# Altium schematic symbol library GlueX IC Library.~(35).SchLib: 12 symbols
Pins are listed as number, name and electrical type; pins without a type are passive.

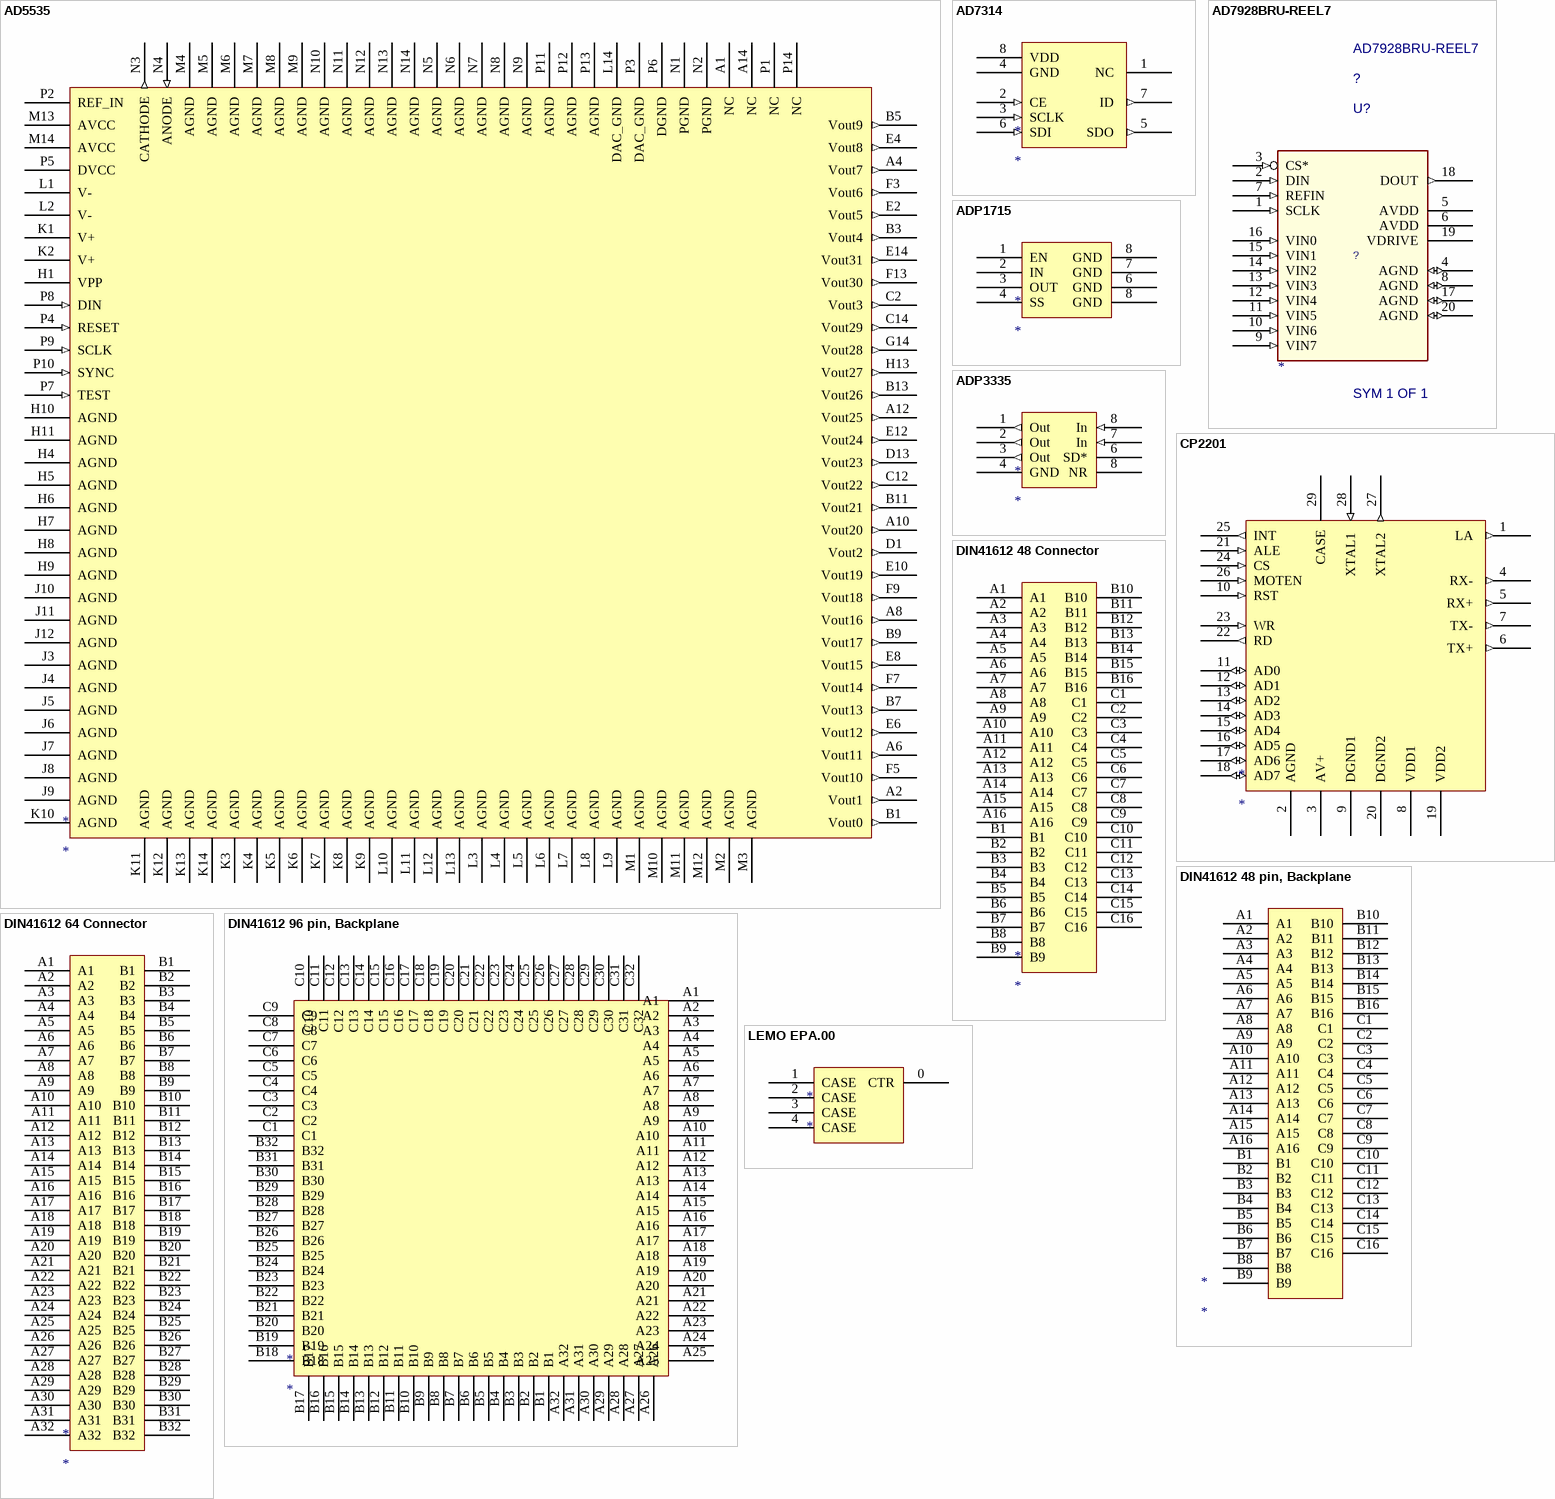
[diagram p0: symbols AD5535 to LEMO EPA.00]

## AD5535
designator *
footprint BC-124
pins: A1 NC, A2 Vout1 (out), A4 Vout7 (out), A6 Vout11 (out), A8 Vout16 (out), A10 Vout20 (out), A12 Vout25 (out), A14 NC, B1 Vout0 (out), B3 Vout4 (out), B5 Vout9 (out), B7 Vout13 (out), B9 Vout17 (out), B11 Vout21 (out), B13 Vout26 (out), C2 Vout3 (out), C12 Vout22 (out), C14 Vout29 (out), D1 Vout2 (out), D13 Vout23 (out), E2 Vout5 (out), E4 Vout8 (out), E6 Vout12 (out), E8 Vout15 (out), E10 Vout19 (out), E12 Vout24 (out), E14 Vout31 (out), F3 Vout6 (out), F5 Vout10 (out), F7 Vout14 (out), F9 Vout18 (out), F13 Vout30 (out), G14 Vout28 (out), H1 VPP (power), H4 AGND, H5 AGND, H6 AGND, H7 AGND, H8 AGND, H9 AGND, H10 AGND, H11 AGND, H13 Vout27 (out), J3 AGND, J4 AGND, J5 AGND, J6 AGND, J7 AGND, J8 AGND, J9 AGND, J10 AGND, J11 AGND, J12 AGND, K1 V+ (power), K2 V+ (power), K3 AGND, K4 AGND, K5 AGND, K6 AGND, K7 AGND, K8 AGND, K9 AGND, K10 AGND, K11 AGND, K12 AGND, K13 AGND, K14 AGND, L1 V- (power), L2 V- (power), L3 AGND, L4 AGND, L5 AGND, L6 AGND, L7 AGND, L8 AGND, L9 AGND, L10 AGND, L11 AGND, L12 AGND, L13 AGND, L14 DAC_GND, M1 AGND, M2 AGND, M3 AGND, M4 AGND, M5 AGND, M6 AGND, M7 AGND, M8 AGND, M9 AGND, M10 AGND, M11 AGND, M12 AGND, M13 AVCC (power), M14 AVCC (power), N1 PGND, N2 PGND, N3 CATHODE (out), N4 ANODE (in), N5 AGND, N6 AGND, N7 AGND, N8 AGND, N9 AGND, N10 AGND, N11 AGND, N12 AGND, N13 AGND, N14 AGND, P1 NC, P2 REF_IN (hiz), P3 DAC_GND, P4 RESET (in), P5 DVCC (power), P6 DGND, P7 TEST (in), P8 DIN (in), P9 SCLK (in), P10 SYNC (in), P11 AGND, P12 AGND, P13 AGND, P14 NC

## AD7314
designator *
footprint RM-8
pins: 1 NC , 2 CE (in), 3 SCLK  (in), 4 GND  (power), 5 SDO  (out), 6 SDI  (in), 7 ID  (out), 8 VDD  (power)

## AD7928BRU-REEL7
designator U?  SymName: AD7928BRU-REEL7  SlotXofY: SYM 1 OF 1
footprint RU-20
pins: 1 SCLK (in), 2 DIN (in), 3 CS* (in), 4 AGND (io), 5 AVDD (power), 6 AVDD (power), 7 REFIN (in), 8 AGND (io), 9 VIN7 (in), 10 VIN6 (in), 11 VIN5 (in), 12 VIN4 (in), 13 VIN3 (in), 14 VIN2 (in), 15 VIN1 (in), 16 VIN0 (in), 17 AGND (io), 18 DOUT (out), 19 VDRIVE (power), 20 AGND (io)

## ADP1715
designator *
footprint R-8_M (8-Pin Narrow Body Small Outline Integrated Circuit 1.27 mm Pitch, IPC Low Density)
pins: 1 EN, 2 IN, 3 OUT, 4 SS, 6 GND, 7 GND, 8 GND, 8 GND

## ADP3335
designator *
footprint R-8_M (8-Pin Narrow Body Small Outline Integrated Circuit 1.27 mm Pitch, IPC Low Density)
pins: 1 Out (out), 2 Out (out), 3 Out (out), 4 GND (power), 6 SD* (hiz), 7 In (in), 8 In (in), 8 NR

## CP2201
designator *
footprint QFN50P500X500-28W1L (QFN, 28-Leads, Body 5x5mm, Pitch 0.5mm, IPC High Density)
footprint QFN50P500X500-28V1N (QFN, 28-Leads, Body 5x5mm, Pitch 0.5mm, IPC Medium Density)
pins: 1 LA  (out), 2 AGND  (power), 3 AV+  (power), 4 RX-  (out), 5 RX+  (out), 6 TX+  (out), 7 TX-  (out), 8 VDD1  (power), 9 DGND1  (power), 10 RST  (in), 11 AD0  (io), 12 AD1  (io), 13 AD2  (io), 14 AD3  (io), 15 AD4  (io), 16 AD5  (io), 17 AD6  (io), 18 AD7  (io), 19 VDD2  (power), 20 DGND2  (power), 21 ALE  (in), 22 RD  (out), 23 WR  (in), 24 CS  (in), 25 INT  (out), 26 MOTEN  (in), 27 XTAL2  (out), 28 XTAL1  (in), 29 CASE (power)

## DIN41612 48 Connector
designator *
footprint EURO2.54-2H48 (Connector; DIN 41612, Type 2C, Thru-Hole; Rows a+b+c, 48 Position; Right Angle)
pins: A1, A2, A3, A4, A5, A6, A7, A8, A9, A10, A11, A12, A13, A14, A15, A16, B1, B2, B3, B4, B5, B6, B7, B8, B9, B10, B11, B12, B13, B14, B15, B16, C1, C2, C3, C4, C5, C6, C7, C8, C9, C10, C11, C12, C13, C14, C15, C16

## DIN41612 48 pin, Backplane
designator *
footprint EURO2.54-2V48 (Connector; DIN 41612, Type 2C, Thru-Hole; Rows a+b+c, 48 Position; Vertical)
pins: A1, A2, A3, A4, A5, A6, A7, A8, A9, A10, A11, A12, A13, A14, A15, A16, B1, B2, B3, B4, B5, B6, B7, B8, B9, B10, B11, B12, B13, B14, B15, B16, C1, C2, C3, C4, C5, C6, C7, C8, C9, C10, C11, C12, C13, C14, C15, C16

## DIN41612 64 Connector
designator *
footprint EURO2.54-2H64A (Connector; DIN 41612, Type B, Thru-Hole; Rows a+b, 64 Position; Right Angle)
pins: A1, A2, A3, A4, A5, A6, A7, A8, A9, A10, A11, A12, A13, A14, A15, A16, A17, A18, A19, A20, A21, A22, A23, A24, A25, A26, A27, A28, A29, A30, A31, A32, B1, B2, B3, B4, B5, B6, B7, B8, B9, B10, B11, B12, B13, B14, B15, B16, B17, B18, B19, B20, B21, B22, B23, B24, B25, B26, B27, B28, B29, B30, B31, B32

## DIN41612 96 pin, Backplane
designator *
footprint EURO2.54-2V96 (Connector; DIN 41612, Type C, Thru-Hole; Rows a+b+c, 96 Position; Vertical)
pins: A1, A2, A3, A4, A5, A6, A7, A8, A9, A10, A11, A12, A13, A14, A15, A16, A17, A18, A19, A20, A21, A22, A23, A24, A25, A26, A27, A28, A29, A30, A31, A32, B1, B2, B3, B4, B5, B6, B7, B8, B9, B10, B11, B12, B13, B14, B15, B16, B17, B18, B19, B20, B21, B22, B23, B24, B25, B26, B27, B28, B29, B30, B31, B32, C1, C2, C3, C4, C5, C6, C7, C8, C9, C10, C11, C12, C13, C14, C15, C16, C17, C18, C19, C20, C21, C22, C23, C24, C25, C26, C27, C28, C29, C30, C31, C32

## LEMO EPA.00
designator *
footprint PCBComponent_1
pins: 0 CTR, 1 CASE, 2 CASE, 3 CASE, 4 CASE

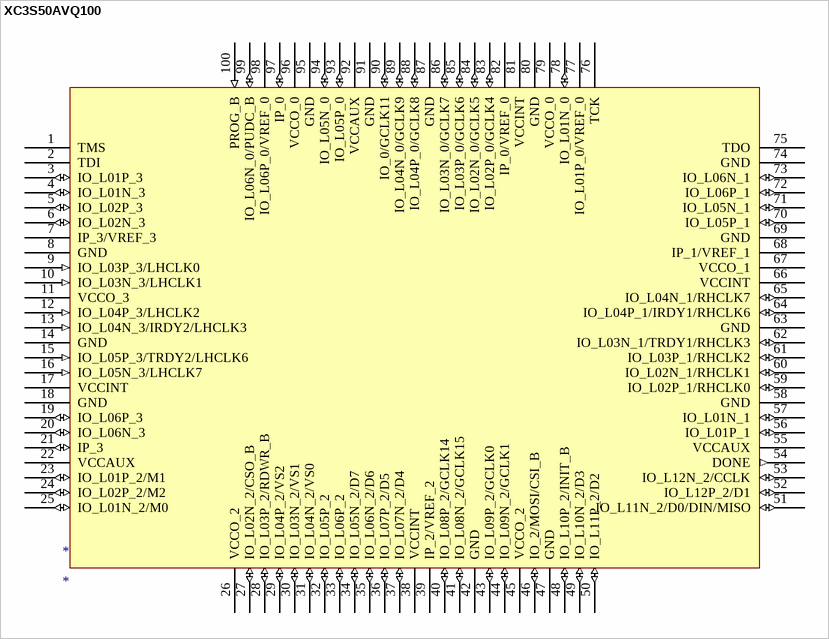
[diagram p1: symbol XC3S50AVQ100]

## XC3S50AVQ100
designator *
footprint VQ100_L (100-Pin Very Thin Quad Flat Pack (VQ100), IPC High Density)
pins: 1 TMS (power), 2 TDI (power), 3 IO_L01P_3 (io), 4 IO_L01N_3 (io), 5 IO_L02P_3 (io), 6 IO_L02N_3 (io), 7 IP_3/VREF_3 (hiz), 8 GND, 9 IO_L03P_3/LHCLK0 (in), 10 IO_L03N_3/LHCLK1 (in), 11 VCCO_3 (power), 12 IO_L04P_3/LHCLK2 (in), 13 IO_L04N_3/IRDY2/LHCLK3 (in), 14 GND (power), 15 IO_L05P_3/TRDY2/LHCLK6 (in), 16 IO_L05N_3/LHCLK7 (in), 17 VCCINT (power), 18 GND (power), 19 IO_L06P_3 (io), 20 IO_L06N_3 (io), 21 IP_3 (io), 22 VCCAUX (power), 23 IO_L01P_2/M1 (io), 24 IO_L02P_2/M2 (io), 25 IO_L01N_2/M0 (io), 26 VCCO_2 (power), 27 IO_L02N_2/CSO_B (io), 28 IO_L03P_2/RDWR_B (io), 29 IO_L04P_2/VS2 (io), 30 IO_L03N_2/VS1 (io), 31 IO_L04N_2/VS0 (io), 32 IO_L05P_2 (io), 33 IO_L06P_2 (io), 34 IO_L05N_2/D7 (io), 35 IO_L06N_2/D6 (io), 36 IO_L07P_2/D5 (io), 37 IO_L07N_2/D4 (io), 38 VCCINT (power), 39 IP_2/VREF_2 (hiz), 40 IO_L08P_2/GCLK14 (io), 41 IO_L08N_2/GCLK15 (io), 42 GND (power), 43 IO_L09P_2/GCLK0 (io), 44 IO_L09N_2/GCLK1 (io), 45 VCCO_2 (power), 46 IO_2/MOSI/CSI_B (io), 47 GND (power), 48 IO_L10P_2/INIT_B (io), 49 IO_L10N_2/D3 (io), 50 IO_L11P_2/D2 (io), 51 IO_L11N_2/D0/DIN/MISO (io), 52 IO_L12P_2/D1 (io), 53 IO_L12N_2/CCLK (io), 54 DONE (out), 55 VCCAUX (power), 56 IO_L01P_1 (io), 57 IO_L01N_1 (io), 58 GND (power), 59 IO_L02P_1/RHCLK0 (io), 60 IO_L02N_1/RHCLK1 (io), 61 IO_L03P_1/RHCLK2 (io), 62 IO_L03N_1/TRDY1/RHCLK3 (io), 63 GND (power), 64 IO_L04P_1/IRDY1/RHCLK6 (io), 65 IO_L04N_1/RHCLK7 (io), 66 VCCINT (power), 67 VCCO_1 (power), 68 IP_1/VREF_1 (hiz), 69 GND (power), 70 IO_L05P_1 (io), 71 IO_L05N_1 (io), 72 IO_L06P_1 (io), 73 IO_L06N_1 (io), 74 GND (power), 75 TDO (power), 76 TCK (power), 77 IO_L01P_0/VREF_0 (hiz), 78 IO_L01N_0 (io), 79 VCCO_0 (power), 80 GND (power), 81 VCCINT (power), 82 IP_0/VREF_0 (hiz), 83 IO_L02P_0/GCLK4 (io), 84 IO_L02N_0/GCLK5 (io), 85 IO_L03P_0/GCLK6 (io), 86 IO_L03N_0/GCLK7 (io), 87 GND, 88 IO_L04P_0/GCLK8 (io), 89 IO_L04N_0/GCLK9 (io), 90 IO_0/GCLK11 (io), 91 GND, 92 VCCAUX, 93 IO_L05P_0 (io), 94 IO_L05N_0 (io), 95 GND, 96 VCCO_0, 97 IP_0 (io), 98 IO_L06P_0/VREF_0 (power), 99 IO_L06N_0/PUDC_B (io), 100 PROG_B (in)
